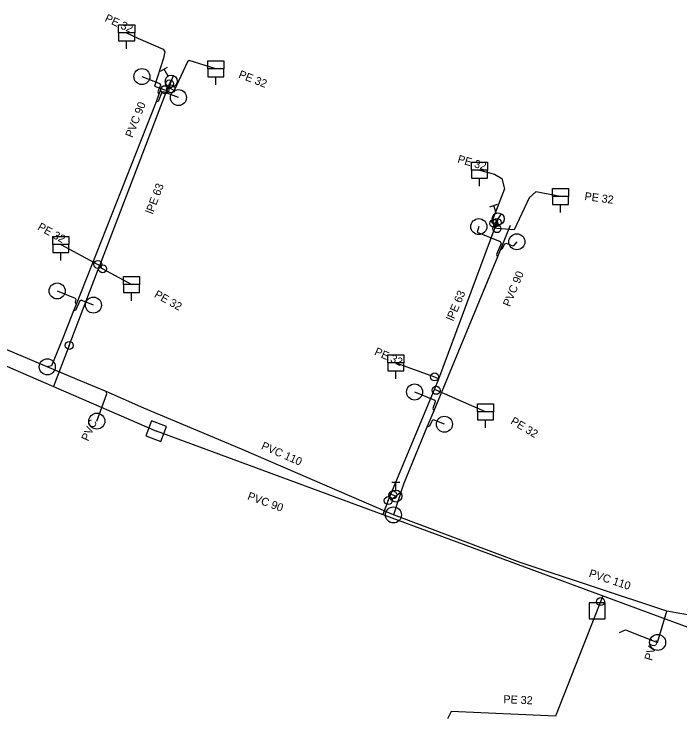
# Model space of a CAD drawing. Extents: x -686883 to -686397, y -1053920 to -1053689.
# Drawn here: x -686646.7 to -686563.6, y -1053776.7 to -1053688.7 of the extents above; entities that cross this region are included whole.
import ezdxf

# ---------------------------------------------------------------- set-up
doc = ezdxf.new("R2010")
doc.units = 0
doc.layers.add('Level 0', color=7, linetype='Continuous')

msp = doc.modelspace()

# ---------------------------------------------------------------- linework, layer by layer
at = {"layer": 'Level 0'}
for p, q in [((-686632.62, -1053691.05), (-686631.24, -1053691.74)), ((-686632.62, -1053693.05), (-686632.62, -1053692.05)), ((-686631.24, -1053691.74), (-686628.06, -1053693.11)), ((-686628.06, -1053693.11), (-686627.86, -1053693.44)), ((-686628.03, -1053694.23), (-686629.14, -1053697.72)), ((-686627.86, -1053693.44), (-686628.03, -1053694.23)), ((-686625.04, -1053694.68), (-686626.71, -1053698.27)), ((-686624.84, -1053694.5), (-686625.04, -1053694.68)), ((-686621.51, -1053695.57), (-686624.84, -1053694.5)), ((-686628.389, -1053695.857), (-686627.532, -1053695.342)), ((-686627.446, -1053696.457), (-686627.96, -1053695.599)), ((-686630.72, -1053696.53), (-686628.49, -1053697.41)), ((-686627.327, -1053697.799), (-686626.791, -1053696.398)), ((-686621.51, -1053697.57), (-686621.51, -1053696.57)), ((-686629.14, -1053697.72), (-686627.87, -1053698.16)), ((-686628.41, -1053697.6), (-686628.71, -1053698.44)), ((-686628.22, -1053697.82), (-686628.59, -1053698.74)), ((-686628.49, -1053697.41), (-686628.41, -1053697.6)), ((-686627.46, -1053697.94), (-686627.27, -1053697.45)), ((-686627.27, -1053697.45), (-686627.06, -1053697.1)), ((-686635.96, -1053720.11), (-686627.6, -1053698.26)), ((-686628.71, -1053698.44), (-686628.59, -1053698.74)), ((-686628.21, -1053698.49), (-686628.69, -1053699.62)), ((-686628.03, -1053698.41), (-686628.21, -1053698.49)), ((-686626.16, -1053699.15), (-686628.03, -1053698.41)), ((-686627.87, -1053698.16), (-686627.6, -1053698.26)), ((-686627.6, -1053698.26), (-686627.46, -1053697.94)), ((-686627.09, -1053698.06), (-686627.46, -1053697.94)), ((-686626.71, -1053698.27), (-686627.09, -1053698.06)), ((-686628.59, -1053698.74), (-686628.95, -1053699.67)), ((-686628.95, -1053699.67), (-686638.93, -1053724.96)), ((-686628.69, -1053699.62), (-686628.95, -1053699.67)), ((-686588.61, -1053708.19), (-686586.74, -1053708.69)), ((-686588.61, -1053710.19), (-686588.61, -1053709.19)), ((-686586.74, -1053708.69), (-686585.81, -1053709.24)), ((-686585.81, -1053709.24), (-686585.49, -1053710.55)), ((-686585.49, -1053710.55), (-686587.1, -1053714.76)), ((-686581.57, -1053710.93), (-686582.4, -1053711.65)), ((-686578.5, -1053711.51), (-686581.57, -1053710.93)), ((-686582.4, -1053711.65), (-686584.29, -1053715.67)), ((-686587.288, -1053712.788), (-686586.339, -1053712.472)), ((-686586.497, -1053713.578), (-686586.813, -1053712.63)), ((-686578.5, -1053713.51), (-686578.5, -1053712.51)), ((-686586.672, -1053714.914), (-686585.845, -1053713.663)), ((-686586.41, -1053714.74), (-686586.26, -1053714.29)), ((-686588.68, -1053715.26), (-686588.87, -1053715.94)), ((-686587.1, -1053714.76), (-686586.8, -1053714.86)), ((-686586.8, -1053714.86), (-686586.49, -1053714.97)), ((-686586.68, -1053715.43), (-686586.5, -1053715.01)), ((-686586.5, -1053715.01), (-686586.49, -1053714.97)), ((-686586.49, -1053714.97), (-686586.41, -1053714.74)), ((-686584.76, -1053715.13), (-686586.02, -1053718.18)), ((-686593.68, -1053734.25), (-686586.68, -1053715.43)), ((-686588.87, -1053715.94), (-686586.01, -1053717.13)), ((-686586.42, -1053715.51), (-686586.68, -1053715.43)), ((-686584.29, -1053715.67), (-686586.42, -1053715.51)), ((-686586.01, -1053717.13), (-686585.91, -1053717.36)), ((-686583.94, -1053717.15), (-686584.38, -1053717.71)), ((-686640.83, -1053717.49), (-686636.21, -1053719.97)), ((-686585.91, -1053717.36), (-686586.49, -1053718.74)), ((-686585.49, -1053717.46), (-686585.79, -1053718.08)), ((-686585.24, -1053717.35), (-686585.49, -1053717.46)), ((-686584.38, -1053717.71), (-686585.24, -1053717.35)), ((-686640.83, -1053719.49), (-686640.83, -1053718.49)), ((-686586.49, -1053718.74), (-686586.37, -1053719.04)), ((-686586.02, -1053718.18), (-686586.37, -1053719.04)), ((-686585.79, -1053718.08), (-686586.02, -1053718.18)), ((-686586.37, -1053719.04), (-686594.31, -1053738.27)), ((-686639.78, -1053730.09), (-686636.03, -1053720.29)), ((-686636.21, -1053719.97), (-686635.96, -1053720.11)), ((-686636.03, -1053720.29), (-686635.96, -1053720.11)), ((-686635.62, -1053720.52), (-686636.03, -1053720.29)), ((-686632.03, -1053722.5), (-686635.62, -1053720.52)), ((-686641.29, -1053723.29), (-686639.04, -1053724.18)), ((-686639.04, -1053724.18), (-686638.96, -1053724.36)), ((-686632.03, -1053724.5), (-686632.03, -1053723.5)), ((-686638.93, -1053724.96), (-686639.24, -1053725.76)), ((-686638.96, -1053724.36), (-686639.06, -1053724.71)), ((-686639.06, -1053724.71), (-686638.93, -1053724.96)), ((-686638.47, -1053724.53), (-686638.99, -1053725.73)), ((-686638.29, -1053724.45), (-686638.47, -1053724.53)), ((-686636.77, -1053725.05), (-686638.29, -1053724.45)), ((-686664.83, -1053725.24), (-686641.74, -1053735.22)), ((-686639.24, -1053725.76), (-686640.59, -1053729.18)), ((-686638.99, -1053725.73), (-686639.24, -1053725.76)), ((-686640.59, -1053729.18), (-686641.99, -1053732.64)), ((-686642.52, -1053732.76), (-686649.61, -1053729.79)), ((-686639.78, -1053730.09), (-686641.74, -1053735.22)), ((-686641.99, -1053732.64), (-686642.52, -1053732.76)), ((-686638.81, -1053734.32), (-686642.52, -1053732.76)), ((-686599.04, -1053732.27), (-686594.2, -1053734.02)), ((-686599.04, -1053734.27), (-686599.04, -1053733.27)), ((-686635.19, -1053735.84), (-686638.81, -1053734.32)), ((-686594.2, -1053734.02), (-686593.68, -1053734.25)), ((-686594.2, -1053735.57), (-686593.68, -1053734.25)), ((-686641.74, -1053735.22), (-686628.91, -1053740.77)), ((-686599.64, -1053748.66), (-686594.2, -1053735.57)), ((-686594, -1053735.69), (-686594.2, -1053735.57)), ((-686636.34, -1053739.54), (-686635.08, -1053736.11)), ((-686630.46, -1053737.92), (-686635.19, -1053735.84)), ((-686635.08, -1053736.11), (-686635.19, -1053735.84)), ((-686596.7, -1053735.9), (-686594.19, -1053736.94)), ((-686587.83, -1053738.37), (-686594, -1053735.69)), ((-686594.11, -1053737.12), (-686594.44, -1053737.97)), ((-686594.19, -1053736.94), (-686594.11, -1053737.12)), ((-686618.28, -1053743.02), (-686630.46, -1053737.92)), ((-686594.31, -1053738.27), (-686595.15, -1053740.31)), ((-686594.44, -1053737.97), (-686594.31, -1053738.27)), ((-686629.518, -1053739.504), (-686630.216, -1053741.378)), ((-686627.644, -1053740.202), (-686629.518, -1053739.504)), ((-686594.52, -1053739.45), (-686594.83, -1053740.18)), ((-686594.34, -1053739.37), (-686594.52, -1053739.45)), ((-686592.97, -1053739.93), (-686594.34, -1053739.37)), ((-686587.83, -1053740.37), (-686587.83, -1053739.37)), ((-686628.94, -1053740.76), (-686600.67, -1053751.2)), ((-686628.94, -1053740.76), (-686600.67, -1053751.2)), ((-686628.342, -1053742.076), (-686627.644, -1053740.202)), ((-686595.15, -1053740.31), (-686598.08, -1053747.41)), ((-686594.83, -1053740.18), (-686595.15, -1053740.31)), ((-686630.216, -1053741.378), (-686628.342, -1053742.076)), ((-686599.33, -1053751.25), (-686618.28, -1053743.02)), ((-686599.53, -1053747.14), (-686598.53, -1053747.14)), ((-686598.08, -1053747.41), (-686599.33, -1053751.25)), ((-686599.03, -1053748.14), (-686599.03, -1053747.14)), ((-686599.98, -1053749.45), (-686599.64, -1053748.66)), ((-686599.64, -1053748.66), (-686599.4, -1053748.75)), ((-686599.618, -1053749.352), (-686598.438, -1053748.426)), ((-686599.4, -1053748.75), (-686599.03, -1053748.89)), ((-686599.98, -1053749.45), (-686600.67, -1053751.2)), ((-686600.67, -1053751.2), (-686561.26, -1053765.76)), ((-686600.67, -1053751.2), (-686561.26, -1053765.76)), ((-686583.53, -1053757.17), (-686599.33, -1053751.25)), ((-686565.24, -1053763.24), (-686583.53, -1053757.17)), ((-686573.2, -1053761.35), (-686579.11, -1053776.35)), ((-686572.93, -1053762.2), (-686574.93, -1053762.2)), ((-686574.93, -1053762.2), (-686574.93, -1053764.2)), ((-686572.93, -1053764.2), (-686572.93, -1053762.2)), ((-686566.37, -1053767.16), (-686565.24, -1053763.24)), ((-686553.73, -1053765.35), (-686565.24, -1053763.24)), ((-686574.93, -1053764.2), (-686572.93, -1053764.2)), ((-686571.12, -1053765.91), (-686570.4, -1053765.6)), ((-686570.4, -1053765.6), (-686566.37, -1053767.16)), ((-686592.14, -1053775.8), (-686592.59, -1053776.71)), ((-686579.11, -1053776.35), (-686592.14, -1053775.8))]:
    msp.add_line(p, q, dxfattribs=at)
for points in [[(-686633.62, -1053691.05), (-686633.62, -1053690.05), (-686631.62, -1053690.05), (-686631.62, -1053691.05)], [(-686622.51, -1053695.57), (-686622.51, -1053694.57), (-686620.51, -1053694.57), (-686620.51, -1053695.57)], [(-686589.61, -1053708.19), (-686589.61, -1053707.19), (-686587.61, -1053707.19), (-686587.61, -1053708.19)], [(-686579.5, -1053711.51), (-686579.5, -1053710.51), (-686577.5, -1053710.51), (-686577.5, -1053711.51)], [(-686641.83, -1053717.49), (-686641.83, -1053716.49), (-686639.83, -1053716.49), (-686639.83, -1053717.49)], [(-686633.03, -1053722.5), (-686633.03, -1053721.5), (-686631.03, -1053721.5), (-686631.03, -1053722.5)], [(-686600.04, -1053732.27), (-686600.04, -1053731.27), (-686598.04, -1053731.27), (-686598.04, -1053732.27)], [(-686588.83, -1053738.37), (-686588.83, -1053737.37), (-686586.83, -1053737.37), (-686586.83, -1053738.37)]]:
    msp.add_lwpolyline(points, dxfattribs=at)
for points in [[(-686633.62, -1053692.05), (-686631.62, -1053692.05), (-686631.62, -1053691.05), (-686633.62, -1053691.05)], [(-686622.51, -1053696.57), (-686620.51, -1053696.57), (-686620.51, -1053695.57), (-686622.51, -1053695.57)], [(-686589.61, -1053709.19), (-686587.61, -1053709.19), (-686587.61, -1053708.19), (-686589.61, -1053708.19)], [(-686579.5, -1053712.51), (-686577.5, -1053712.51), (-686577.5, -1053711.51), (-686579.5, -1053711.51)], [(-686641.83, -1053718.49), (-686639.83, -1053718.49), (-686639.83, -1053717.49), (-686641.83, -1053717.49)], [(-686633.03, -1053723.5), (-686631.03, -1053723.5), (-686631.03, -1053722.5), (-686633.03, -1053722.5)], [(-686600.04, -1053733.27), (-686598.04, -1053733.27), (-686598.04, -1053732.27), (-686600.04, -1053732.27)], [(-686588.83, -1053739.37), (-686586.83, -1053739.37), (-686586.83, -1053738.37), (-686588.83, -1053738.37)]]:
    msp.add_lwpolyline(points, close=True, dxfattribs=at)
for centre, radius in [((-686630.72, -1053696.53), 1), ((-686627.06, -1053697.1), 0.75), ((-686627.87, -1053698.16), 0.5), ((-686627.27, -1053697.45), 0.5), ((-686627.09, -1053698.06), 0.5), ((-686626.16, -1053699.15), 1), ((-686586.26, -1053714.29), 0.75), ((-686588.68, -1053715.26), 1), ((-686586.8, -1053714.86), 0.5), ((-686586.41, -1053714.74), 0.5), ((-686586.42, -1053715.51), 0.5), ((-686583.94, -1053717.15), 1), ((-686636.21, -1053719.97), 0.5), ((-686635.62, -1053720.52), 0.5), ((-686641.29, -1053723.29), 1), ((-686636.77, -1053725.05), 1), ((-686639.78, -1053730.09), 0.5), ((-686642.52, -1053732.76), 1), ((-686594.2, -1053734.02), 0.5), ((-686596.7, -1053735.9), 1), ((-686594, -1053735.69), 0.5), ((-686636.34, -1053739.54), 1), ((-686592.97, -1053739.93), 1), ((-686599.4, -1053748.75), 0.5), ((-686599.03, -1053748.89), 0.75), ((-686599.98, -1053749.45), 0.5), ((-686599.33, -1053751.25), 1), ((-686573.49, -1053762.07), 0.5), ((-686566.37, -1053767.16), 1)]:
    msp.add_circle(centre, radius, dxfattribs=at)

# ---------------------------------------------------------------- texts
for s, rotation, p in [('PE 32', 335.51, (-686635.43, -1053689.59)), ('PE 32', 338.846, (-686618.74, -1053696.63)), ('PVC 90', 68.465, (-686631.9, -1053704.22)), ('PE 32', 344.072, (-686591.41, -1053707.24)), ('lPE 63', 69.063, (-686629.37, -1053713.77)), ('PE 32', 352.412, (-686575.54, -1053711.93)), ('PE 32', 330.751, (-686643.81, -1053715.57)), ('PVC 90', 67.564, (-686584.8, -1053725.33)), ('PE 32', 330.709, (-686629.26, -1053724)), ('lPE 63', 66.801, (-686591.88, -1053727.12)), ('PE 32', 336.14, (-686601.79, -1053731.21)), ('PE 32', 329.036, (-686584.81, -1053739.8)), ('PVC ', 65.406, (-686637.42, -1053742.12)), ('PVC 110', 336.263, (-686615.91, -1053742.97)), ('PVC 90', 339.731, (-686617.63, -1053749.28)), ('PVC 110', 341.64, (-686575.02, -1053758.94)), ('PVC ', 73.92, (-686567.09, -1053769.51)), ('PE 32', 357.583, (-686585.63, -1053774.74))]:
    msp.add_text(s, height=1, rotation=rotation, dxfattribs=at).set_placement(p)

doc.saveas('drawing.dxf')
